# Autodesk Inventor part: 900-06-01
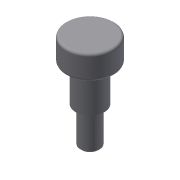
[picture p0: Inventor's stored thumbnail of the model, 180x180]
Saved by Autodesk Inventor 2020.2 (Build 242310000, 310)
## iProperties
Created: 2015-10
Part Number: 900-06-01
Material: Ogólny
Document SubType Name: Modeling
Designer: F.Stasiak
Density: 1 g/cm^3
Appearance: Domyślna
Catalog Web Link: www.expertbooks.pl
Manager: www.cadconsulting.pl
Company: Fabian Stasiak CAD Consulting
Author: F.Stasiak
Subject: Zbiór ćwiczeń. Autodesk Inventor 2020. Kurs Professional
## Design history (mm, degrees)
sketch "Szkic1"
  geometry: C1 r 20 at (0, 0); 1 further point
  constraints: 1 centre point, 1 coincident
  dimensions: "d0" = 40 diameter of C1
extrude "Wyciągnięcie proste1" new body sketch "Szkic1" distance "d1" = 150; taper "d2" = 0 deg
sketch "Szkic2"
  geometry: C1 r 20 at (0, 0) reference; C2 r 50 at (0, 0)
  constraints: 1 centre point, 1 coincident
  dimensions: "d3" = 100 diameter of C2
extrude "Wyciągnięcie proste2" join sketch "Szkic2" distance "d4" = 50; taper "d5" = 0 deg
sketch "Szkic3"
  geometry: C1 r 20 at (0, 0) reference; C2 r 20 at (0, 0) reference; C3 r 30 at (0, 0)
  constraints: 1 centre point, 1 coincident
  dimensions: "d6" = 60 diameter of C3
extrude "Wyciągnięcie proste3" join sketch "Szkic3" distance "d7" = 75; taper "d8" = 0 deg
fillet "Zaokrąglenie1" dims "d9" = 5
chamfer "Faza1" distance "d10" = 3; stored, may be unused: second distance "d11" = 2, angle "d12" = 45 deg
node "Bryła1"
